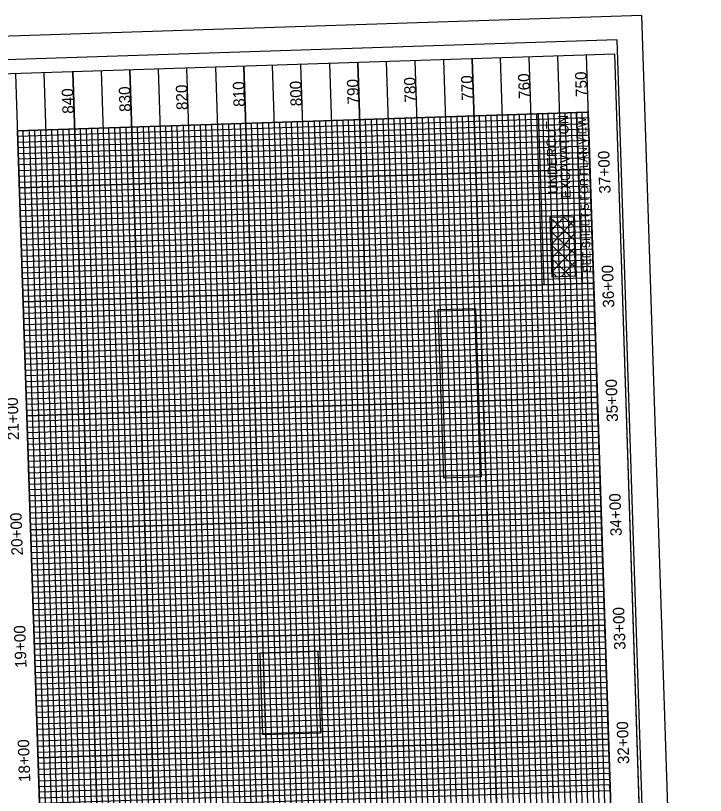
# Model space of a CAD drawing. Extents: x 1627314 to 1628469, y 762309 to 764212.
# Drawn here: x 1627865 to 1628469, y 763361 to 764044 of the extents above; entities that cross this region are included whole.
import ezdxf

# ---------------------------------------------------------------- set-up
doc = ezdxf.new("R2010")
doc.units = 0
for name, color, linetype in [('Exist Vertical Profile Horizontal Axis Label Major', 7, 'Continuous'), ('Exist Vertical Profile Vertical Axis Label', 7, 'Continuous'), ('Prop DSN Text', 7, 'Continuous'), ('Prop Grid Mask', 7, 'Continuous'), ('Prop XS Undercut Exc Hatch', 7, 'Continuous'), ('Prop XSC Text', 7, 'Continuous'), ('Sheet DOT Grid CELL', 7, 'Continuous'), ('Sheet Layout Profile Border Port 2', 7, 'Continuous'), ('Sheet Plot Border Inside CELL', 7, 'Continuous'), ('Sheet Plot Border Outside CELL', 7, 'Continuous'), ('Sheet Profile CELL', 7, 'Continuous'), ('Sheet Profile Grid Major CELL', 7, 'Continuous'), ('Sheet Profile Grid Middle CELL', 7, 'Continuous'), ('Sheet Profile Grid Minor CELL', 7, 'Continuous')]:
    doc.layers.add(name, color=color, linetype=linetype)

msp = doc.modelspace()

# ---------------------------------------------------------------- linework, layer by layer
at = {"layer": 'Prop Grid Mask'}
for points in [[(1628327.86, 763808.36), (1628322.96, 763958.36), (1628356.37, 763959.45), (1628361.28, 763809.45)], [(1628356.37, 763959.45), (1628361.12, 763814.53), (1628371.11, 763814.85), (1628366.37, 763959.78)], [(1628355.54, 763816.19), (1628353.85, 763868.02), (1628332.89, 763867.33), (1628334.59, 763815.5)], [(1628239.96, 763639.01), (1628235.13, 763786.66), (1628267.91, 763787.73), (1628272.73, 763640.09)], [(1628081.47, 763413.87), (1628079.12, 763485.82), (1628129.74, 763487.48), (1628132.09, 763415.53)]]:
    msp.add_lwpolyline(points, close=True, dxfattribs=at)
at = {"layer": 'Prop XS Undercut Exc Hatch'}
for p, q in [((1628332.9, 763867.14), (1628333.09, 763867.34)), ((1628354.52, 763847.45), (1628333.28, 763867.34)), ((1628333.29, 763855.12), (1628345.1, 763867.73)), ((1628333.69, 763843.11), (1628353.95, 763864.75)), ((1628354.13, 763859.47), (1628345.29, 763867.74)), ((1628354.91, 763835.44), (1628333.27, 763855.7)), ((1628334.08, 763831.1), (1628354.35, 763852.73)), ((1628355.3, 763823.42), (1628333.67, 763843.69)), ((1628334.47, 763819.08), (1628354.74, 763840.72)), ((1628350.76, 763816.03), (1628334.06, 763831.67)), ((1628343.03, 763815.78), (1628355.13, 763828.7)), ((1628338.75, 763815.64), (1628334.45, 763819.66)), ((1628355.04, 763816.17), (1628355.53, 763816.69))]:
    msp.add_line(p, q, dxfattribs=at)
at = {"layer": 'Sheet DOT Grid CELL'}
for p, q in [((1628313.83, 762507.28), (1628264.79, 764006.37)), ((1628363.8, 762508.92), (1628314.77, 764008)), ((1628113.93, 762500.74), (1628064.9, 763999.83)), ((1628163.91, 762502.38), (1628114.87, 764001.46)), ((1628213.88, 762504.01), (1628164.85, 764003.1)), ((1628263.85, 762505.65), (1628214.82, 764004.73)), ((1627914.04, 762494.2), (1627865.01, 763993.29)), ((1627964.01, 762495.84), (1627914.98, 763994.92)), ((1628013.99, 762497.47), (1627964.95, 763996.56)), ((1628063.96, 762499.11), (1628014.93, 763998.19)), ((1627866.64, 763943.43), (1628366.37, 763959.78)), ((1627868.27, 763893.46), (1628368, 763909.8)), ((1627869.91, 763843.48), (1628369.64, 763859.83)), ((1627871.54, 763793.51), (1628371.27, 763809.86)), ((1627873.18, 763743.54), (1628372.91, 763759.88)), ((1627874.81, 763693.56), (1628374.54, 763709.91)), ((1627876.44, 763643.59), (1628376.18, 763659.94)), ((1627878.08, 763593.62), (1628377.81, 763609.96)), ((1627879.71, 763543.64), (1628379.45, 763559.99)), ((1627881.35, 763493.67), (1628381.08, 763510.02)), ((1627882.98, 763443.7), (1628382.72, 763460.04)), ((1627884.62, 763393.72), (1628384.35, 763410.07))]:
    msp.add_line(p, q, dxfattribs=at)
at = {"layer": 'Sheet Layout Profile Border Port 2'}
for points in [[(1627912.41, 762544.18), (1627866.64, 763943.43), (1628366.37, 763959.78), (1628412.14, 762560.52)], [(1627912.41, 762544.18), (1628412.14, 762560.52), (1628366.37, 763959.78), (1627866.64, 763943.43)]]:
    msp.add_lwpolyline(points, close=True, dxfattribs=at)
at = {"layer": 'Sheet Plot Border Inside CELL'}
msp.add_lwpolyline([(1628446.34, 762357.53), (1628391.86, 764023.14), (1627337.33, 763988.65), (1627391.81, 762323.04)], close=True, dxfattribs=at)
at = {"layer": 'Sheet Plot Border Outside CELL'}
msp.add_lwpolyline([(1628469.21, 762345.27), (1628413.63, 764044.37), (1627314.22, 764008.4), (1627369.79, 762309.31)], close=True, dxfattribs=at)
at = {"layer": 'Sheet Profile CELL'}
for p, q in [((1628364.74, 764009.75), (1628413.77, 762510.55)), ((1628438.76, 762511.37), (1628389.72, 764010.57)), ((1627914.04, 762494.2), (1627865, 763993.4))]:
    msp.add_line(p, q, dxfattribs=at)
msp.add_lwpolyline([(1627340.28, 763976.24), (1627389.32, 762477.04), (1628438.76, 762511.37), (1628389.72, 764010.57)], close=True, dxfattribs=at)
at = {"layer": 'Sheet Profile Grid Major CELL'}
for p, q in [((1627868.27, 763893.46), (1627866.64, 763943.43)), ((1628368, 763909.8), (1628368, 763909.8)), ((1627871.54, 763793.51), (1627869.91, 763843.48)), ((1627874.81, 763693.56), (1627873.18, 763743.54)), ((1627878.08, 763593.62), (1627876.44, 763643.59)), ((1627881.35, 763493.67), (1627879.71, 763543.64)), ((1627884.62, 763393.72), (1627882.98, 763443.7))]:
    msp.add_line(p, q, dxfattribs=at)
for points in [[(1628264.79, 764006.48), (1628313.83, 762507.28), (1628313.83, 762507.28), (1628363.8, 762508.92), (1628314.76, 764008.11)], [(1628364.74, 764009.75), (1628413.77, 762510.55)], [(1628064.9, 763999.94), (1628113.93, 762500.74), (1628163.91, 762502.38), (1628114.87, 764001.58)], [(1628164.84, 764003.21), (1628213.88, 762504.01), (1628263.85, 762505.65), (1628214.82, 764004.85)], [(1627914.98, 763995.04), (1627964.01, 762495.84)], [(1627964.95, 763996.67), (1628013.99, 762497.47), (1628063.96, 762499.11), (1628014.92, 763998.31)], [(1628385.99, 763360.1), (1628384.35, 763410.07), (1627884.62, 763393.72), (1627882.98, 763443.7), (1628382.72, 763460.04), (1628381.08, 763510.02), (1627881.35, 763493.67), (1627879.71, 763543.64), (1628379.45, 763559.99), (1628377.81, 763609.96), (1627878.08, 763593.62), (1627876.44, 763643.59), (1628376.18, 763659.94), (1628374.54, 763709.91), (1627874.81, 763693.56), (1627873.18, 763743.54), (1628372.91, 763759.88), (1628371.27, 763809.86), (1627871.54, 763793.51), (1627869.91, 763843.48), (1628369.64, 763859.83), (1628368, 763909.8), (1628368, 763909.8), (1627868.27, 763893.46), (1627866.64, 763943.43), (1628366.37, 763959.78)]]:
    msp.add_lwpolyline(points, dxfattribs=at)
at = {"layer": 'Sheet Profile Grid Middle CELL'}
for points in [[(1628239.8, 764005.66), (1628288.84, 762506.46), (1628338.81, 762508.1), (1628289.78, 764007.3)], [(1628339.75, 764008.93), (1628388.79, 762509.73)], [(1628039.91, 763999.12), (1628088.95, 762499.93), (1628138.92, 762501.56), (1628089.88, 764000.76)], [(1628139.86, 764002.39), (1628188.89, 762503.2), (1628238.87, 762504.83), (1628189.83, 764004.03)], [(1627939.03, 762495.02), (1627889.99, 763994.22)], [(1627939.96, 763995.85), (1627989, 762496.66), (1628038.97, 762498.29), (1627989.94, 763997.49)], [(1627887.07, 763318.76), (1627885.44, 763368.74), (1628385.17, 763385.08), (1628383.53, 763435.06), (1627883.8, 763418.71), (1627882.17, 763468.68), (1628381.9, 763485.03), (1628380.26, 763535), (1627880.53, 763518.66), (1627878.9, 763568.63), (1628378.63, 763584.98), (1628376.99, 763634.95), (1627877.26, 763618.6), (1627875.63, 763668.58), (1628375.36, 763684.92), (1628373.73, 763734.9), (1627873.99, 763718.55), (1627872.36, 763768.52), (1628372.09, 763784.87), (1628370.46, 763834.84), (1627870.72, 763818.5), (1627869.09, 763868.47), (1628368.82, 763884.82), (1628367.19, 763934.79), (1627867.45, 763918.44)]]:
    msp.add_lwpolyline(points, dxfattribs=at)
at = {"layer": 'Sheet Profile Grid Minor CELL'}
for p, q in [((1628326.39, 763958.47), (1628372.16, 762559.22)), ((1628377.16, 762559.38), (1628331.39, 763958.63)), ((1628336.39, 763958.8), (1628382.16, 762559.54)), ((1628392.15, 762559.87), (1628346.38, 763959.12)), ((1628351.38, 763959.29), (1628397.15, 762560.03)), ((1628402.14, 762560.2), (1628356.37, 763959.45)), ((1628361.37, 763959.61), (1628361.37, 763959.61)), ((1628407.14, 762560.36), (1628361.37, 763959.61)), ((1628167.27, 762552.51), (1628121.5, 763951.77)), ((1628126.5, 763951.93), (1628172.27, 762552.68)), ((1628177.26, 762552.84), (1628131.5, 763952.09)), ((1628136.49, 763952.26), (1628182.26, 762553)), ((1628192.26, 762553.33), (1628146.49, 763952.58)), ((1628151.48, 763952.75), (1628197.25, 762553.5)), ((1628202.25, 762553.66), (1628156.48, 763952.91)), ((1628161.48, 763953.07), (1628207.25, 762553.82)), ((1628217.24, 762554.15), (1628171.47, 763953.4)), ((1628176.47, 763953.56), (1628222.24, 762554.31)), ((1628227.24, 762554.48), (1628181.47, 763953.73)), ((1628186.47, 763953.89), (1628232.24, 762554.64)), ((1628242.23, 762554.97), (1628196.46, 763954.22)), ((1628201.46, 763954.38), (1628247.23, 762555.13)), ((1628252.22, 762555.29), (1628206.46, 763954.55)), ((1628211.45, 763954.71), (1628257.22, 762555.46)), ((1628267.22, 762555.78), (1628221.45, 763955.04)), ((1628226.44, 763955.2), (1628272.21, 762555.95)), ((1628277.21, 762556.11), (1628231.44, 763955.36)), ((1628236.44, 763955.53), (1628282.21, 762556.27)), ((1628292.2, 762556.6), (1628246.43, 763955.85)), ((1628251.43, 763956.02), (1628297.2, 762556.76)), ((1628302.2, 762556.93), (1628256.43, 763956.18)), ((1628261.43, 763956.34), (1628307.2, 762557.09)), ((1628317.19, 762557.42), (1628271.42, 763956.67)), ((1628276.42, 763956.83), (1628322.19, 762557.58)), ((1628327.18, 762557.75), (1628281.42, 763957)), ((1628286.41, 763957.16), (1628332.18, 762557.91)), ((1628342.18, 762558.24), (1628296.41, 763957.49)), ((1628301.4, 763957.65), (1628347.17, 762558.4)), ((1628352.17, 762558.56), (1628306.4, 763957.81)), ((1628311.4, 763957.98), (1628357.17, 762558.73)), ((1628367.16, 762559.05), (1628321.39, 763958.3)), ((1627952.38, 762545.49), (1627906.62, 763944.74)), ((1627911.61, 763944.9), (1627957.38, 762545.65)), ((1627967.38, 762545.98), (1627921.61, 763945.23)), ((1627926.6, 763945.39), (1627972.37, 762546.14)), ((1627977.37, 762546.3), (1627931.6, 763945.55)), ((1627936.6, 763945.72), (1627982.37, 762546.47)), ((1627992.36, 762546.79), (1627946.59, 763946.05)), ((1627951.59, 763946.21), (1627997.36, 762546.96)), ((1628002.36, 762547.12), (1627956.59, 763946.37)), ((1627961.59, 763946.54), (1628007.36, 762547.28)), ((1628017.35, 762547.61), (1627971.58, 763946.86)), ((1627976.58, 763947.03), (1628022.35, 762547.77)), ((1628027.34, 762547.94), (1627981.58, 763947.19)), ((1627986.57, 763947.35), (1628032.34, 762548.1)), ((1628042.34, 762548.43), (1627996.57, 763947.68)), ((1628001.56, 763947.84), (1628047.33, 762548.59)), ((1628052.33, 762548.75), (1628006.56, 763948.01)), ((1628011.56, 763948.17), (1628057.33, 762548.92)), ((1628067.32, 762549.25), (1628021.55, 763948.5)), ((1628026.55, 763948.66), (1628072.32, 762549.41)), ((1628077.32, 762549.57), (1628031.55, 763948.82)), ((1628036.55, 763948.99), (1628082.32, 762549.74)), ((1628092.31, 762550.06), (1628046.54, 763949.31)), ((1628051.54, 763949.48), (1628097.31, 762550.23)), ((1628102.3, 762550.39), (1628056.54, 763949.64)), ((1628061.53, 763949.8), (1628107.15, 762550.55)), ((1628117.3, 762550.88), (1628071.53, 763950.13)), ((1628076.52, 763950.3), (1628122.29, 762551.04)), ((1628127.29, 762551.21), (1628081.52, 763950.46)), ((1628086.52, 763950.62), (1628132.29, 762551.37)), ((1628142.28, 762551.7), (1628096.51, 763950.95)), ((1628101.51, 763951.11), (1628147.28, 762551.86)), ((1628152.28, 762552.02), (1628106.51, 763951.28)), ((1628111.51, 763951.44), (1628157.28, 762552.19)), ((1627917.4, 762544.34), (1627871.63, 763943.59)), ((1627876.63, 763943.76), (1627922.4, 762544.5)), ((1627927.4, 762544.67), (1627881.63, 763943.92)), ((1627886.63, 763944.08), (1627932.4, 762544.83)), ((1627942.39, 762545.16), (1627896.62, 763944.41)), ((1627901.62, 763944.57), (1627947.39, 762545.32))]:
    msp.add_line(p, q, dxfattribs=at)
for points in [[(1628374.87, 763699.91), (1628374.71, 763704.91), (1627874.97, 763688.57), (1627874.65, 763698.56), (1628374.38, 763714.91), (1628374.22, 763719.9), (1627874.48, 763703.56), (1627874.32, 763708.56), (1628374.05, 763724.9), (1628373.89, 763729.9), (1627874.16, 763713.55), (1627873.83, 763723.55), (1628373.56, 763739.89), (1628373.4, 763744.89), (1627873.67, 763728.54), (1627873.5, 763733.54), (1628373.24, 763749.89), (1628373.07, 763754.89), (1627873.34, 763738.54), (1627873.01, 763748.53), (1628372.74, 763764.88), (1628372.58, 763769.88), (1627872.85, 763753.53), (1627872.68, 763758.53), (1628372.42, 763774.87), (1628372.25, 763779.87), (1627872.52, 763763.53), (1627872.19, 763773.52), (1628371.93, 763789.87), (1628371.76, 763794.86), (1627872.03, 763778.52), (1627871.87, 763783.52), (1628371.6, 763799.86), (1628371.44, 763804.86), (1627871.7, 763788.51), (1627871.38, 763798.51), (1628371.11, 763814.85), (1628370.95, 763819.85), (1627871.21, 763803.5), (1627871.05, 763808.5), (1628370.78, 763824.85), (1628370.62, 763829.85), (1627870.89, 763813.5), (1627870.56, 763823.49), (1628370.29, 763839.84), (1628370.13, 763844.84), (1627870.4, 763828.49), (1627870.23, 763833.49), (1628369.97, 763849.83), (1628369.8, 763854.83), (1627870.07, 763838.49), (1627869.74, 763848.48), (1628369.48, 763864.83), (1628369.31, 763869.82), (1627869.58, 763853.48), (1627869.42, 763858.48), (1628369.15, 763874.82), (1628368.99, 763879.82), (1627869.25, 763863.47), (1627868.93, 763873.47), (1628368.66, 763889.81), (1628368.49, 763894.81), (1627868.76, 763878.46), (1627868.6, 763883.46), (1628368.33, 763899.81), (1628368.17, 763904.81), (1627868.43, 763888.46), (1627868.11, 763898.45), (1628367.84, 763914.8), (1628367.68, 763919.8), (1627867.94, 763903.45), (1627867.78, 763908.45), (1628367.51, 763924.79), (1628367.35, 763929.79), (1627867.62, 763913.45), (1627867.29, 763923.44), (1628367.02, 763939.79), (1628366.86, 763944.78), (1627867.13, 763928.44), (1627866.96, 763933.44), (1628366.7, 763949.78), (1628366.53, 763954.78), (1627866.8, 763938.43), (1627866.64, 763943.43)], [(1628384.84, 763395.08), (1627885.11, 763378.73), (1627884.94, 763383.73), (1628384.68, 763400.08), (1628384.51, 763405.07), (1627884.78, 763388.73), (1627884.45, 763398.72), (1628384.19, 763415.07), (1628384.02, 763420.06), (1627884.29, 763403.72), (1627884.13, 763408.72), (1628383.86, 763425.06), (1628383.7, 763430.06), (1627883.96, 763413.71), (1627883.64, 763423.71), (1628383.37, 763440.05), (1628383.21, 763445.05), (1627883.47, 763428.7), (1627883.31, 763433.7), (1628383.04, 763450.05), (1628382.88, 763455.05), (1627883.15, 763438.7), (1627882.82, 763448.69), (1628382.55, 763465.04), (1628382.39, 763470.04), (1627882.66, 763453.69), (1627882.49, 763458.69), (1628382.23, 763475.04), (1628382.06, 763480.03), (1627882.33, 763463.69), (1627882, 763473.68), (1628381.74, 763490.03), (1628381.57, 763495.02), (1627881.84, 763478.68), (1627881.68, 763483.68), (1628381.41, 763500.02), (1628381.24, 763505.02), (1627881.51, 763488.67), (1627881.19, 763498.67), (1628380.92, 763515.01), (1628380.75, 763520.01), (1627881.02, 763503.66), (1627880.86, 763508.66), (1628380.59, 763525.01), (1628380.43, 763530.01), (1627880.69, 763513.66), (1627880.37, 763523.65), (1628380.1, 763540), (1628379.94, 763545), (1627880.2, 763528.65), (1627880.04, 763533.65), (1628379.77, 763550), (1628379.61, 763554.99), (1627879.88, 763538.65), (1627879.55, 763548.64), (1628379.28, 763564.99), (1628379.12, 763569.98), (1627879.39, 763553.64), (1627879.22, 763558.64), (1628378.96, 763574.98), (1628378.79, 763579.98), (1627879.06, 763563.63), (1627878.73, 763573.63), (1628378.47, 763589.97), (1628378.3, 763594.97), (1627878.57, 763578.62), (1627878.41, 763583.62), (1628378.14, 763599.97), (1628377.98, 763604.97), (1627878.24, 763588.62), (1627877.92, 763598.61), (1628377.65, 763614.96), (1628377.49, 763619.96), (1627877.75, 763603.61), (1627877.59, 763608.61), (1628377.32, 763624.95), (1628377.16, 763629.95), (1627877.43, 763613.61), (1627877.1, 763623.6), (1628376.83, 763639.95), (1628376.67, 763644.94), (1627876.93, 763628.6), (1627876.77, 763633.6), (1628376.5, 763649.94), (1628376.34, 763654.94), (1627876.61, 763638.59), (1627876.28, 763648.59), (1628376.01, 763664.93), (1628375.85, 763669.93), (1627876.12, 763653.58), (1627875.95, 763658.58), (1628375.69, 763674.93), (1628375.52, 763679.93), (1627875.79, 763663.58), (1627875.46, 763673.57), (1628375.2, 763689.92), (1628375.03, 763694.92), (1627875.3, 763678.57), (1627875.14, 763683.57), (1628374.87, 763699.91)], [(1627885.76, 763358.74), (1628385.49, 763375.09), (1628385.33, 763380.09), (1627885.6, 763363.74), (1627885.27, 763373.73), (1628385, 763390.08), (1628384.84, 763395.08)], [(1627886.09, 763348.75), (1628385.82, 763365.09), (1628385.12, 763369.77), (1628385.66, 763370.09), (1627885.93, 763353.75)]]:
    msp.add_lwpolyline(points, dxfattribs=at)

# ---------------------------------------------------------------- texts
at = {"layer": 'Exist Vertical Profile Horizontal Axis Label Major'}
for s, p in [('37+00', (1628386.21, 763888.5)), ('36+00', (1628389.48, 763788.44)), ('35+00', (1628392.76, 763688.38)), ('21+00', (1627868, 763672.32)), ('34+00', (1628396.03, 763588.27)), ('20+00', (1627871.3, 763571.32)), ('33+00', (1628399.29, 763488.54)), ('19+00', (1627874.53, 763472.61)), ('32+00', (1628402.57, 763388.43)), ('18+00', (1627877.8, 763372.69))]:
    msp.add_text(s, height=10, rotation=91.87347, dxfattribs=at).set_placement(p)
at = {"layer": 'Exist Vertical Profile Vertical Axis Label'}
for s, p in [('760', (1628315.71, 763971.56)), ('750', (1628365.68, 763973.19)), ('810', (1628065.8, 763964.58)), ('800', (1628115.81, 763965.02)), ('790', (1628165.79, 763966.65)), ('780', (1628215.76, 763968.29)), ('770', (1628265.73, 763969.92)), ('840', (1627915.92, 763958.48)), ('830', (1627965.89, 763960.12)), ('820', (1628015.87, 763961.75))]:
    msp.add_text(s, height=10, rotation=91.87347, dxfattribs=at).set_placement(p)
at = {"layer": 'Prop DSN Text'}
msp.add_text('SEE SHEET 5 FOR PLAN VIEW', height=7, rotation=91.87347, dxfattribs=at).set_placement((1628369.01, 763819.37))
at = {"layer": 'Prop XSC Text'}
for s, p in [('UNDERCUT', (1628339.99, 763888.32)), ('EXCAVATION', (1628351.28, 763884.23))]:
    msp.add_text(s, height=8.5, rotation=91.87347, dxfattribs=at).set_placement(p)

doc.saveas('drawing.dxf')
